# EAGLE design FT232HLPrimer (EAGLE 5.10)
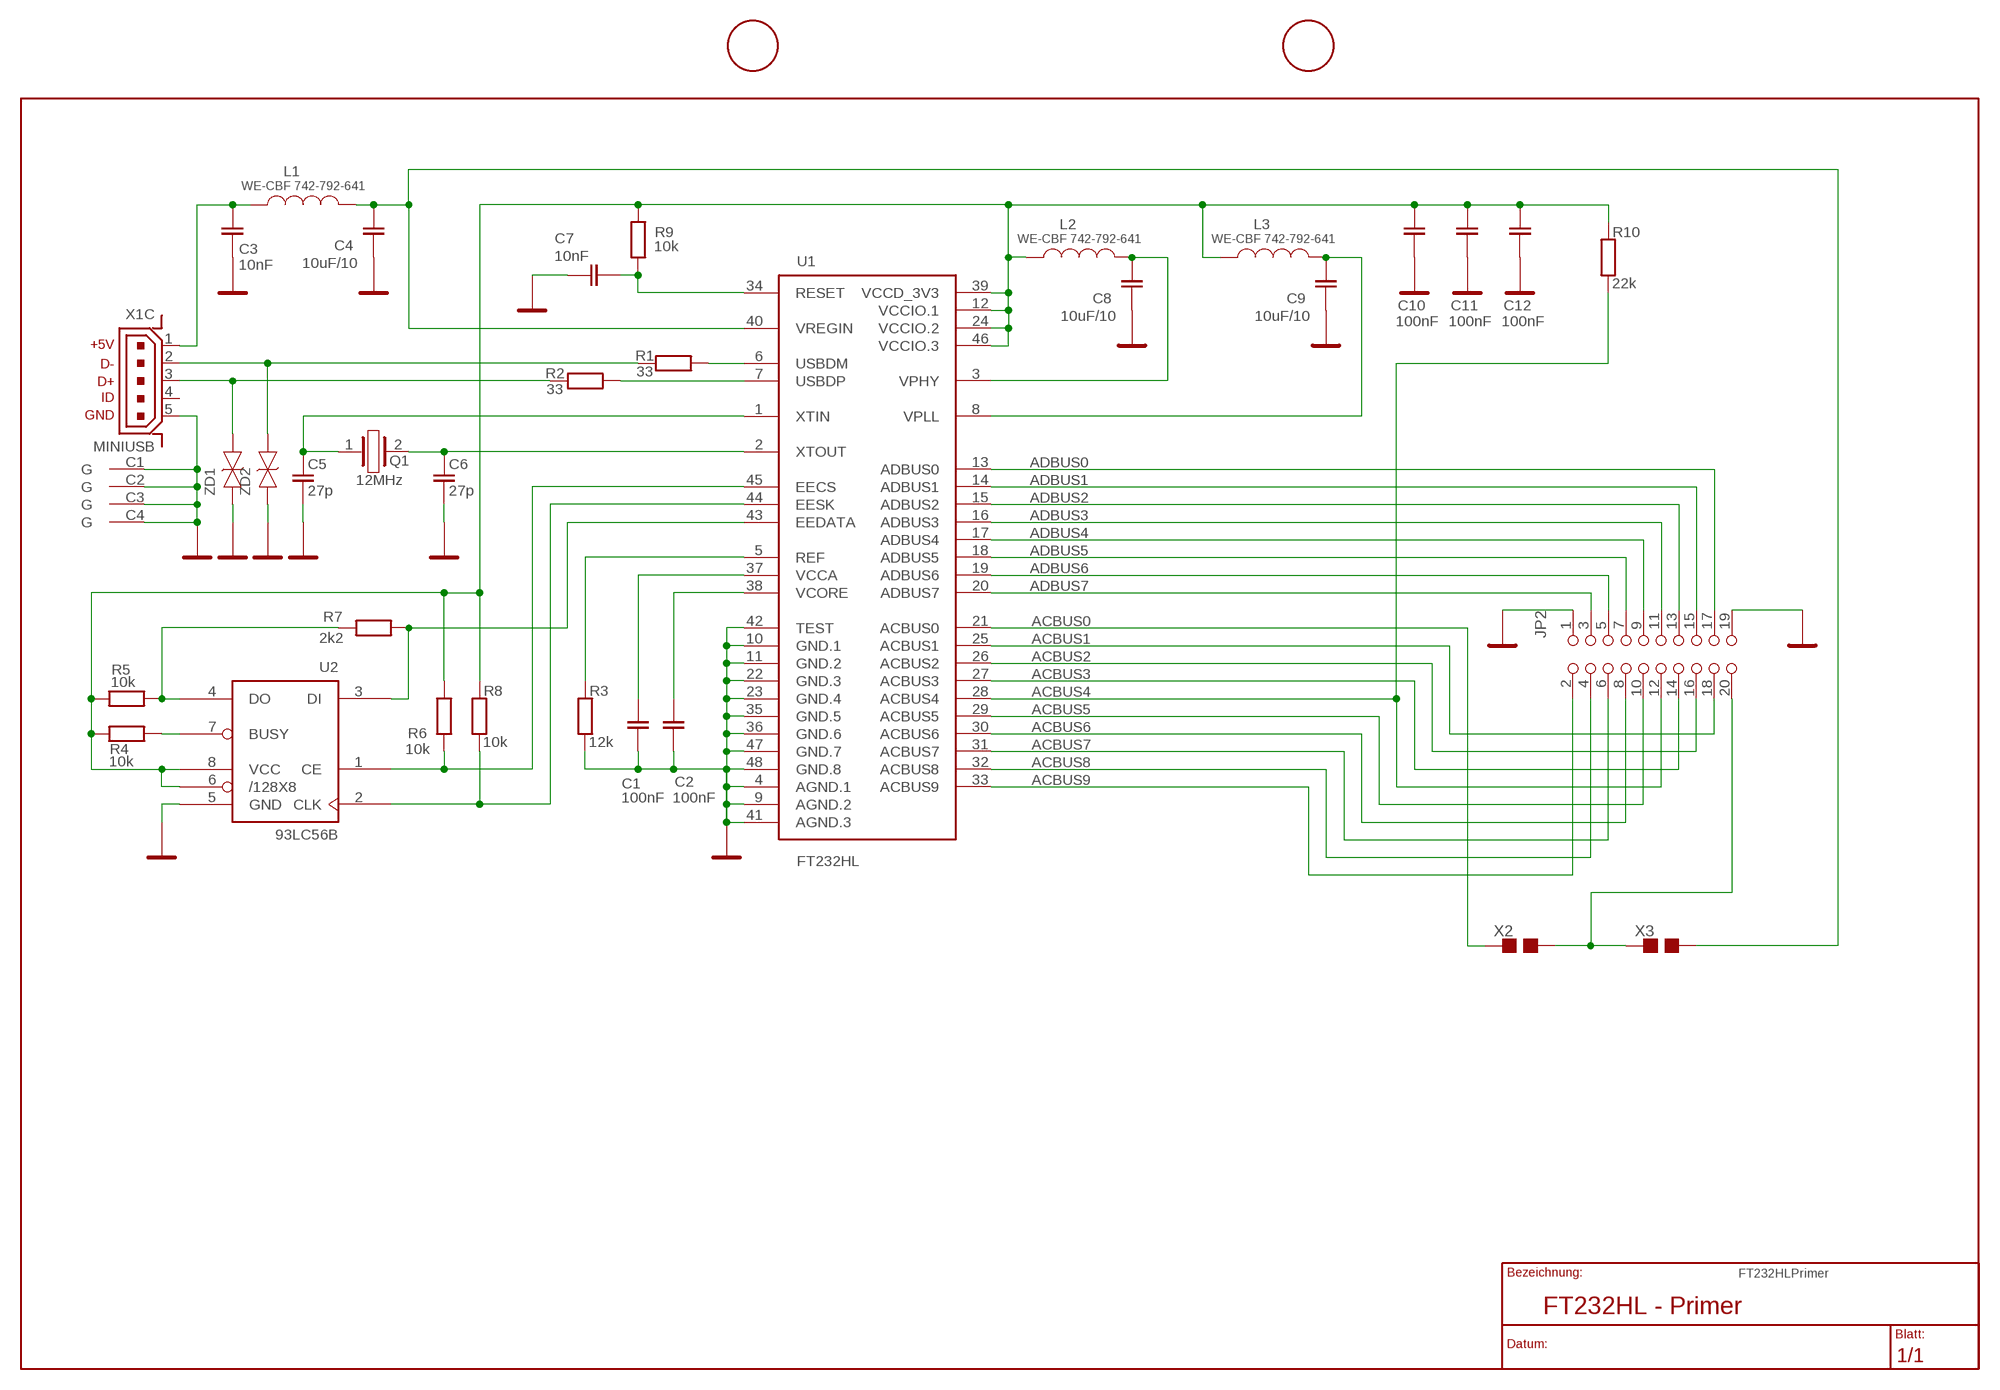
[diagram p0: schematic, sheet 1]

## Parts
C1  100nF  SMD-0603  [SOT-0603]
C2  100nF  SMD-0603  [SOT-0603]
C3  10nF  SMD-0603  [SOT-0603]
C4  10uF/10  SMD-0805  [SOT-0805]
C5  27p  SMD-0603  [SOT-0603]
C6  27p  SMD-0603  [SOT-0603]
C7  10nF  SMD-0603  [SOT-0603]
C8  10uF/10  SMD-0805  [SOT-0805]
C9  10uF/10  SMD-0805  [SOT-0805]
C10  100nF  SMD-0603  [SOT-0603]
C11  100nF  SMD-0603  [SOT-0603]
C12  100nF  SMD-0603  [SOT-0603]
JP2  PINHD-2X10'/90'  [2X10/90]
L1  WE-CBF 742-792-641  SMD-0603  [SMD-0603]
L2  WE-CBF 742-792-641  SMD-0603  [SMD-0603]
L3  WE-CBF 742-792-641  SMD-0603  [SMD-0603]
Q1  12MHz  XTAL'SMD5X3'  [XTAL5X3]
R1  33  SMD-0603  [SMD-0603]
R2  33  SMD-0603  [SMD-0603]
R3  12k  SMD-0603  [SMD-0603]
R4  10k  SMD-0603  [SMD-0603]
R5  10k  SMD-0603  [SMD-0603]
R6  10k  SMD-0603  [SMD-0603]
R7  2k2  SMD-0603  [SMD-0603]
R8  10k  SMD-0603  [SMD-0603]
R9  10k  SMD-0603  [SMD-0603]
R10  22k  SMD-0603  [SMD-0603]
U1  FT232HL  [LQFP48]
U2  93LC56B  93LC66'SO'  [SO-8]
X1  MINIUSB  [UX60A-MB-5SY]
X2  PATCH  [PATCH]
X3  PATCH  [PATCH]
ZD1  PGB1010603  [SUPP0603]
ZD2  PGB1010603  [SUPP0603]

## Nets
ACBUS0: U1.21(ACBUS0) X2.1
ACBUS1: JP2.18 U1.25(ACBUS1)
ACBUS2: JP2.16 U1.26(ACBUS2)
ACBUS3: JP2.14 U1.27(ACBUS3)
ACBUS4: JP2.12 R10.1 U1.28(ACBUS4)
ACBUS5: JP2.10 U1.29(ACBUS5)
ACBUS6: JP2.8 U1.30(ACBUS6)
ACBUS7: JP2.6 U1.31(ACBUS7)
ACBUS8: JP2.4 U1.32(ACBUS8)
ACBUS9: JP2.2 U1.33(ACBUS9)
ADBUS0: JP2.17 U1.13(ADBUS0)
ADBUS1: JP2.15 U1.14(ADBUS1)
ADBUS2: JP2.13 U1.15(ADBUS2)
ADBUS3: JP2.11 U1.16(ADBUS3)
ADBUS4: JP2.9 U1.17(ADBUS4)
ADBUS5: JP2.7 U1.18(ADBUS5)
ADBUS6: JP2.5 U1.19(ADBUS6)
ADBUS7: JP2.3 U1.20(ADBUS7)
CLK: R8.1 U1.44(EESK) U2.2(CLK)
CS: R6.1 U1.45(EECS) U2.1(CE)
D+: R2.2 X1.3 ZD1.2(K)
D-: R1.2 X1.2 ZD2.2(K)
DATA: R7.2 U1.43(EEDATA) U2.3(DI)
GND: C1.1 C2.1 C3.1 C4.1 C5.1 C6.1 C7.1 C8.1 C9.1 C10.1 C11.1 C12.1 JP2.1 JP2.19 R3.1 U1.4(AGND.1) U1.9(AGND.2) U1.10(GND.1) U1.11(GND.2) U1.22(GND.3) U1.23(GND.4) U1.35(GND.5) U1.36(GND.6) U1.41(AGND.3) U1.42(TEST) U1.47(GND.7) U1.48(GND.8) U2.5(GND) X1.5 X1.C1(G) X1.C2(G) X1.C3(G) X1.C4(G) ZD1.1(A) ZD2.1(A)
N$3: R1.1 U1.6(USBDM)
N$4: R2.1 U1.7(USBDP)
N$5: JP2.20 X2.2 X3.1
N$10: C5.2 Q1.1 U1.1(XTIN)
N$11: C6.2 Q1.2 U1.2(XTOUT)
N$12: R5.1 R7.1 U2.4(DO)
N$17: R4.1 U2.7(BUSY)
REF: R3.2 U1.5(REF)
RESET: C7.2 R9.2 U1.34(RESET)
VBUS: C3.2 L1.1 X1.1
VBUS_5V: C4.2 L1.2 U1.40(VREGIN) X3.2
VCCA: C1.2 U1.37(VCCA)
VCCIO: C10.2 C11.2 C12.2 L2.1 L3.1 R4.2 R5.2 R6.2 R8.2 R9.1 R10.2 U1.12(VCCIO.1) U1.24(VCCIO.2) U1.39(VCCD_3V3) U1.46(VCCIO.3) U2.6(/128X8) U2.8(VCC)
VCORE: C2.2 U1.38(VCORE)
VPHY: C8.2 L2.2 U1.3(VPHY)
VPLL: C9.2 L3.2 U1.8(VPLL)
Unconnected: X1.4

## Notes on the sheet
- FT232HL - Primer

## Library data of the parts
C1-C3 C5-C7 C10-C12 = C_KERAM:SMD-0603
C4 C8 C9 = C_KERAM:SMD-0805
JP2 = PINHD-Q:PINHD-2X10
L1-L3 = L:SMD-0603
Q1 = Z_SPECIA:XTAL
R1-R10 = R:SMD-0603
U1 = FTDI:FT232HL
U2 = MIC_CHIP:93LC66
X1 = mini-usb:MINIUSB
X2 X3 = Z_CONNEC:PATCH
ZD1 ZD2 = DIODEN:PGB1010603: Suppressordiode (USB usw.)

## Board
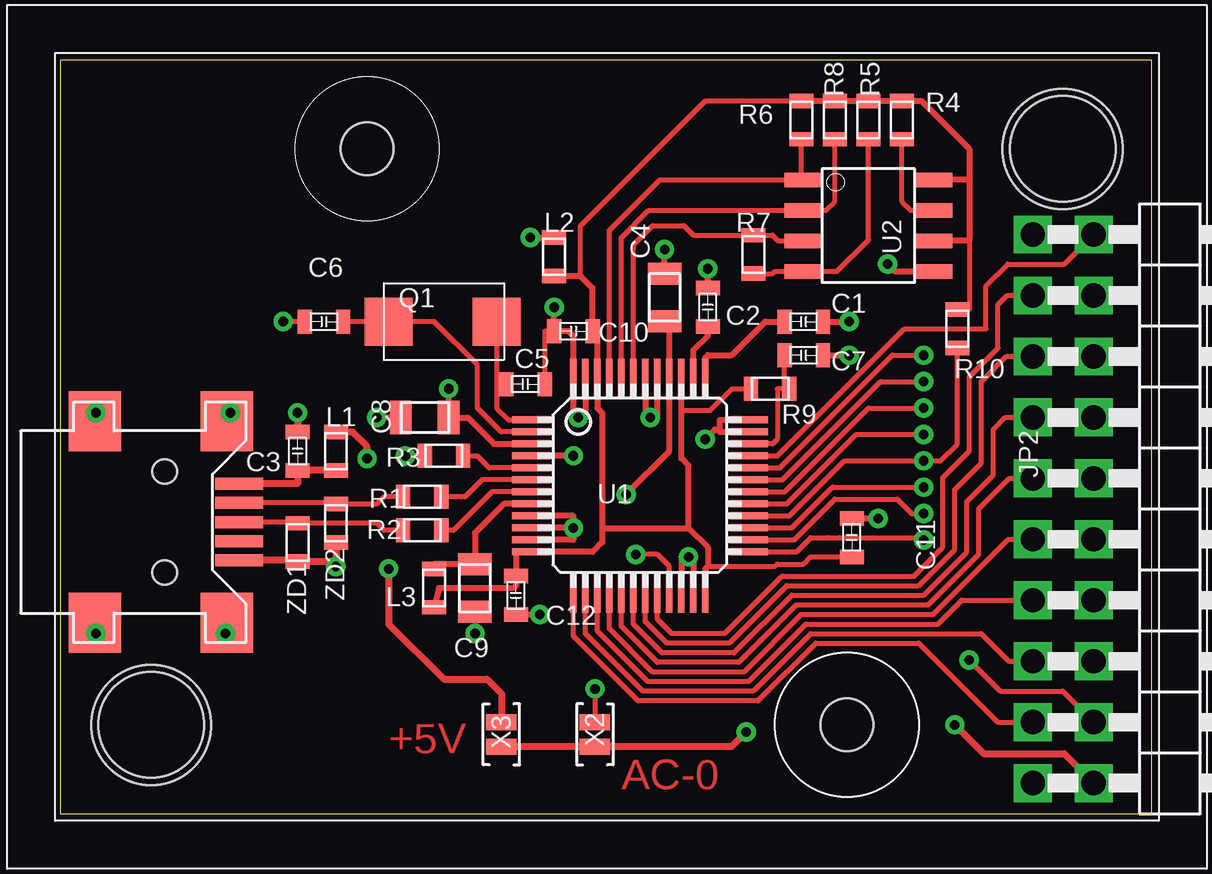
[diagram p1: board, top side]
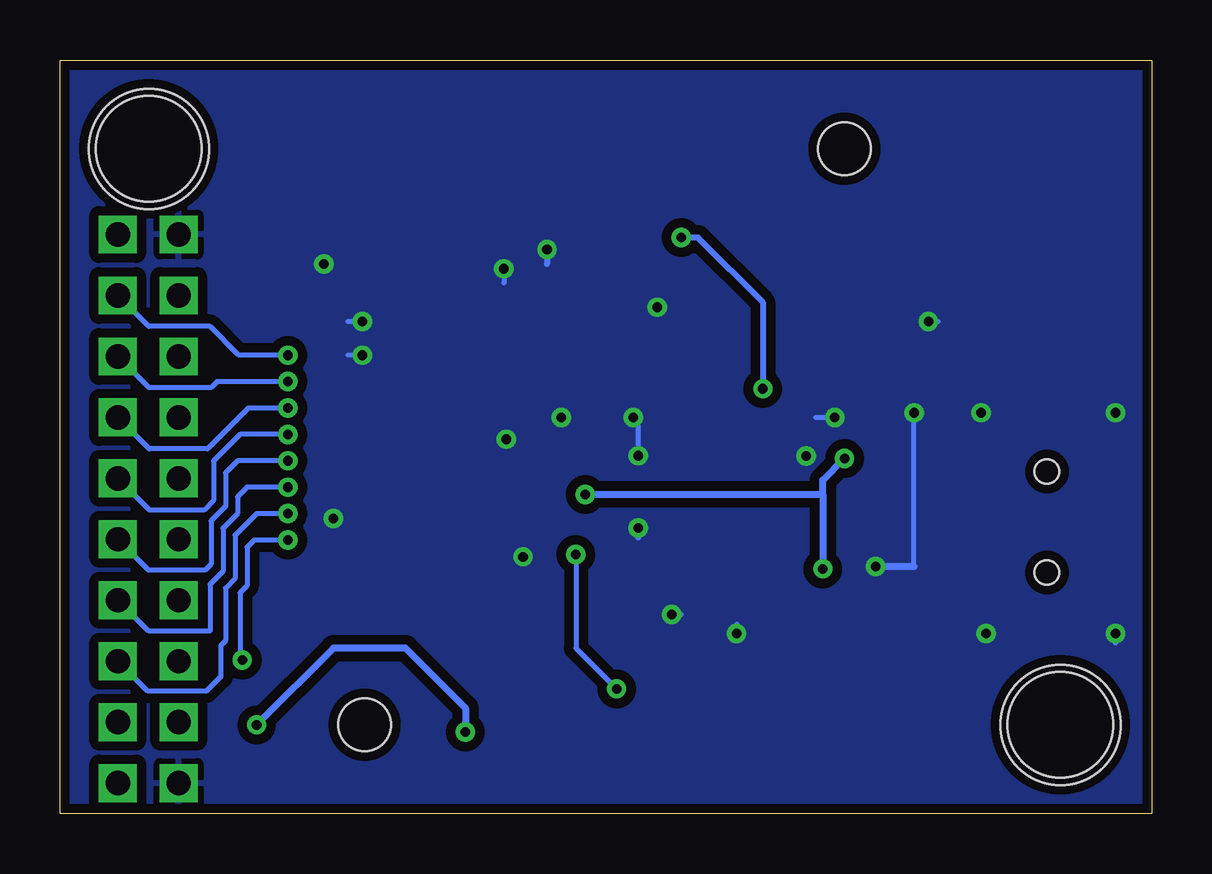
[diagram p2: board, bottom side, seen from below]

Size 45.5 x 31.4 mm. Coordinates in mm from the lower left corner, seen from the top.
Outline: 0,0 45.5,0 45.5,31.4 0,31.4 0,0
Copper layers (1*16): Top 0.035mm / dielectric 1.5mm / Bottom 0.035mm
Design rules "default": minimum track width 0.15mm, minimum drill 0.3mm, track to track 0.15mm, track to pad 0.15mm, pad to pad 0.15mm, via to via 0.15mm, smd to smd 0mil, copper to edge 0.15mm, drill to drill 0.15mm, minimum pad ring 0.15mm, minimum via ring 0.15mm, stop-mask expansion 4mil, vias tented up to drill 0mil, thermal gap 10mil
Holes 5 mm at 3.8,3.7 41.8,27.7

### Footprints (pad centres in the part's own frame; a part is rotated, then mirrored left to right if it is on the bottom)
SOT-0603 = smd 0.6 x 1: 1 -0.8,0; 2 0.8,0
SOT-0805 = smd 0.914 x 1.397: 1 -0.991,0; 2 0.991,0
2X10/90 = drill 1.016 pad 1.575 square: 1 -11.43,-6.35; 2 -11.43,-3.81; 3 -8.89,-6.35; 4 -8.89,-3.81; 5 -6.35,-6.35; 6 -6.35,-3.81; 7 -3.81,-6.35; 8 -3.81,-3.81; 9 -1.27,-6.35; 10 -1.27,-3.81; 11 1.27,-6.35; 12 1.27,-3.81; 13 3.81,-6.35; 14 3.81,-3.81; 15 6.35,-6.35; 16 6.35,-3.81; 17 8.89,-6.35; 18 8.89,-3.81; 19 11.43,-6.35; 20 11.43,-3.81
SMD-0603 = smd 0.6 x 1: 1 -0.8,0; 2 0.8,0
XTAL5X3 = smd 2 x 2: 1 -2.2,0; 2 2.3,0
LQFP48 = smd 1.6 x 0.28: 1 -4.5,2.75; 2 -4.5,2.25; 3 -4.5,1.75; 4 -4.5,1.25; 5 -4.5,0.75; 6 -4.5,0.25; 7 -4.5,-0.25; 8 -4.5,-0.75; 9 -4.5,-1.25; 10 -4.5,-1.75; 11 -4.5,-2.25; 12 -4.5,-2.75; 25 4.55,-2.75; 26 4.55,-2.25; 27 4.55,-1.75; 28 4.55,-1.25; 29 4.55,-0.75; 30 4.55,-0.25; 31 4.55,0.25; 32 4.55,0.75; 33 4.55,1.25; 34 4.55,1.75; 35 4.55,2.25; 36 4.55,2.75 | smd 0.28 x 1.6: 13 -2.75,-4.5; 14 -2.25,-4.5; 15 -1.75,-4.5; 16 -1.25,-4.5; 17 -0.75,-4.5; 18 -0.25,-4.5; 19 0.25,-4.5; 20 0.75,-4.5; 21 1.25,-4.5; 22 1.75,-4.5; 23 2.25,-4.5; 24 2.75,-4.5; 37 2.75,4.5; 38 2.25,4.5; 39 1.75,4.5; 40 1.25,4.5; 41 0.75,4.5; 42 0.25,4.5; 43 -0.25,4.5; 44 -0.75,4.5; 45 -1.25,4.5; 46 -1.75,4.5; 47 -2.25,4.5; 48 -2.75,4.5
SO-8 = smd 0.61 x 1.524: 1 -1.905,-2.743; 2 -0.635,-2.743; 3 0.635,-2.743; 4 1.905,-2.743; 5 1.905,2.743; 6 0.635,2.743; 7 -0.635,2.743; 8 -1.905,2.743
KM201B = hole 4.4: -19,-12; 19,12 | hole 2.2: -10,12; 10,-12
UX60A-MB-5SY = smd 0.5 x 2: 1 -1.6,3.1; 2 -0.8,3.1; 3 0,3.1; 4 0.8,3.1; 5 1.6,3.1 | smd 2.5 x 2.2: C1 -4.2,2.6; C2 -4.2,-2.9; C3 4.2,-2.9; C4 4.2,2.6 | hole 1.016: -2.1,0; 2.1,0
PATCH = smd 0.66 x 1.27: 1 -0.508,0; 2 0.508,0
SUPP0603 = smd 0.6 x 1: 1 -0.8,0; 2 0.8,0

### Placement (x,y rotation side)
C1  31,20.5 180 top
C2  27,21.1 270 top
C3  9.9,15.1 270 top
C4  25.2,21.5 270 top
C5  19.4,17.9 180 top
C6  11,20.5 0 top
C7  31,19.1 180 top
C8  15.2,16.5 0 top
C9  17.3,9.4 90 top
C10  21.4,20.1 0 top
C11  33,11.5 270 top
C12  19,9.1 90 top
JP2  46.9,12.7 270 top
L1  11.5,15.1 90 top
L2  20.6,23.2 90 top
L3  15.6,9.4 90 top
Q1  16,20.5 180 top
R1  15.1,13.2 180 top
R2  15.1,11.8 180 top
R3  16,14.91 0 top
R4  35.1,28.9 90 top
R5  33.7,28.9 90 top
R6  30.9,28.9 90 top
R7  28.9,23.3 90 top
R8  32.3,28.9 90 top
R9  29.6,17.7 0 top
R10  37.4,20.2 90 top
U1  24.15,13.66 0 top
U2  33.7,24.5 270 top
U$21  [KM201B]  22.8,15.7 0 top
X1  4.36,12.15 270 top
X2  22.3,3.3 270 top
X3  18.4,3.3 90 top
ZD1  9.9,11.3 90 top
ZD2  11.5,12.1 90 top

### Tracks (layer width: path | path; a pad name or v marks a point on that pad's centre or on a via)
ACBUS0  (via drill 0.4 pad 0.8)
  Top 0.2: U1.21 25.4,10.3 24.9,10.8 v24,10.8 | v22.3,5.2 X2.1
  Bottom 0.2: v24,10.8 24,6.9 v22.3,5.2
ACBUS1  (via drill 0.4 pad 0.8)
  Top 0.2: U1.25 30.71,10.91 31.3,11.5 32,11.5 32.5,11.5 35.9,11.5 v36,11.4 | JP2.18 41.8,5.1 39.2,5.1 v37.9,6.4
  Bottom 0.2: v37.9,6.4 38,6.5 38,9.2 37.7,9.5 37.7,11.1 37.4,11.4 v36,11.4
ACBUS2  (via drill 0.4 pad 0.8)
  Top 0.2: U1.26 30.61,11.41 32.3,13.1 34.9,13.1 35.5,12.5 v36,12.5
  Bottom 0.2: JP2.16 41.84,5.1 39.4,5.1 38.8,5.7 38.8,7 38.6,7.2 38.6,9.4 38.2,9.8 38.2,11.6 37.3,12.5 v36,12.5
ACBUS3  (via drill 0.4 pad 0.8)
  Top 0.2: U1.27 30.51,11.91 32.2,13.6 v36,13.6
  Bottom 0.2: JP2.14 41.8,7.6 39.25,7.6 39.25,9.55 38.7,10.1 38.7,11.9 38.1,12.5 38.1,13.2 37.7,13.6 v36,13.6
ACBUS4  (via drill 0.4 pad 0.8)
  Top 0.2: U1.28 30.41,12.41 32.7,14.7 v36,14.7 36.7,14.7 37.4,15.4 37.4,16.1 R10.1
  Bottom 0.2: JP2.12 41.81,10.15 39.45,10.15 39.2,10.4 39.2,12.2 38.6,12.8 38.6,14.2 38.1,14.7 v36,14.7
ACBUS5  (via drill 0.4 pad 0.8)
  Top 0.2: U1.29 30.31,12.91 33.2,15.8 v36,15.8
  Bottom 0.2: JP2.10 41.77,12.65 39.5,12.65 39.1,13.05 39.1,14.7 38,15.8 v36,15.8
ACBUS6  (via drill 0.4 pad 0.8)
  Top 0.2: U1.30 30.21,13.41 33.7,16.9 v36,16.9
  Bottom 0.2: JP2.8 41.78,15.2 39.35,15.2 37.65,16.9 v36,16.9
ACBUS7  (via drill 0.4 pad 0.8)
  Top 0.2: U1.31 30.11,13.91 34.2,18 v36,18
  Bottom 0.2: JP2.6 41.79,17.75 39.2,17.75 38.95,18 v36,18
ACBUS8  (via drill 0.4 pad 0.8)
  Top 0.2: U1.32 30.01,14.41 34.7,19.1 v36,19.1
  Bottom 0.2: JP2.4 41.8,20.3 39.25,20.3 38.05,19.1 v36,19.1
ACBUS9
  Top 0.2: U1.33 29.91,14.91 35.2,20.2 36.8,20.2 38.6,20.2 38.6,22 39.5,22.9 41.86,22.9 JP2.2
ADBUS0
  Top 0.2: U1.13 21.4,7.4 24.1,4.7 29.1,4.7 31.5,7.1 35.8,7.1 39.09,3.81 JP2.17
ADBUS1
  Top 0.2: U1.14 21.9,7.5 24.3,5.1 28.9,5.1 31.3,7.5 38.4,7.5 39.55,6.35 JP2.15
ADBUS2
  Top 0.2: U1.15 22.4,7.6 24.5,5.5 28.7,5.5 31.1,7.9 36.6,7.9 37.59,8.89 JP2.13
ADBUS3
  Top 0.2: U1.16 22.9,7.7 24.7,5.9 28.5,5.9 30.9,8.3 36.4,8.3 39.53,11.43 JP2.11
ADBUS4
  Top 0.2: U1.17 23.4,7.8 24.9,6.3 28.3,6.3 30.7,8.7 36.2,8.7 38.3,10.8 38.3,12.7 39.57,13.97 JP2.9
ADBUS5
  Top 0.2: U1.18 23.9,7.9 25.1,6.7 28.1,6.7 30.5,9.1 36,9.1 37.8,10.9 37.8,13 38.9,14.1 38.9,16 39.41,16.51 JP2.7
ADBUS6
  Top 0.2: U1.19 24.4,8 25.3,7.1 27.9,7.1 30.3,9.5 35.8,9.5 37.3,11 37.3,13.5 38.4,14.6 38.4,18 39.45,19.05 JP2.5
ADBUS7
  Top 0.2: U1.20 24.9,8.1 25.5,7.5 27.7,7.5 30.1,9.9 35.6,9.9 36.8,11.1 36.8,14 37.9,15.1 37.9,18.2 39.1,19.4 39.1,21.2 39.49,21.59 JP2.3
CLK
  Top 0.2: R8.1 32.3,25.5 31.94,25.13 U2.2 24.54,25.13 23.4,24 U1.44
CS
  Top 0.2: R6.1 30.9,26.41 U2.1 25.01,26.41 22.9,24.3 U1.45
D+
  Top 0.2: X1.3 9.9,12.15 ZD1.2 13,12.1 13.2,12.1 13.5,11.8 R2.2
D-
  Top 0.2: X1.2 11.5,12.95 ZD2.2 13,12.9 13.2,12.9 13.5,13.2 R1.2
DATA
  Top 0.2: U2.3 29.94,23.86 29.7,24.1 R7.2 26.4,24.1 26,24.5 24.7,24.5 23.9,23.7 U1.43
GND  (via drill 0.4 pad 0.8)
  Top 0.2: 24.4,16.5 v24.6,16.5 | v21.4,11.9 v21.4,11.91 | ZD1.1 9.9,10.55 | X1.C3 1.46,7.54 v1.5,7.5 | X1.C4 6.96,7.56 v6.9,7.5 | X1.C2 1.46,16.66 v1.5,16.7 | X1.C1 6.96,16.56 v7.1,16.7 | R3.1 v14.41,14.91 v14.4,14.9 | U1.10 | C9.1 v17.3,7.5 | C5.1 20.2,20.1 C10.1 | C6.1 v9.3,20.5
  Top 0.25: v21.4,14.91 U1.4 | U1.47 21.9,16.5 v21.6,16.5 21.4,16.5 U1.48 21.4,19.9 21.2,20.1 C10.1 v20.6,21.1 | U1.41 24.9,16.5 v24.6,16.5 | U1.42 24.4,16.5 | U1.35 27.5,15.91 27.5,16 | U1.36 27.5,16.41 27.5,16 | v26.9,15.6 27.3,16 27.5,16 | U1.11 21.4,11.41 v21.4,11.9 21.4,12.41 U1.9 | v21.4,11.91 U1.10 | U1.23 26.4,10.7 v26.2,10.7 25.9,10.7 U1.22 | C11.1 v34.1,12.3 | U2.5 34.8,22.59 v34.5,22.9 | C8.1 v13.2,16.5 | C12.1 v20,8.3 | C4.1 v25.2,23.5 | C2.1 v27,22.7 | C1.1 v32.9,20.5 | C7.1 v32.9,19.1
  Top 0.3: 9.9,10.55 X1.5 | 11.5,10.5 ZD1.1 | 11.5,10.5 v11.5,10.3 | ZD2.1 11.5,10.5 | v9.9,16.7 C3.1
  Bottom 0.2: v21.4,14.91 21.4,16.5 v21.6,16.5 | v26.9,15.6 26.6,15.6 | v26.2,10.7 26.2,10.9 | 9.9,10.3 v9.9,16.7 | v1.5,7.5 1.5,7.1 | v6.9,7.5 6.9,7.3 | v1.5,16.7 1.5,16.9 | v7.1,16.7 7.1,16.9 | v14.4,14.9 14.6,14.9 | v34.1,12.3 33.8,12.3 | v34.5,22.9 34.3,23.1 | v13.2,16.5 14,16.5 | v17.3,7.5 17.3,7.9 | v20,8.3 19.6,8.3 | v27,22.7 27,22.1 | v32.9,20.5 33.5,20.5 | v32.9,19.1 33.5,19.1 | v9.3,20.5 8.9,20.5
  Bottom 0.25: v24.6,16.5 24.8,16.5 | v21.4,11.9 21.4,11.5 | v25.2,23.5 25.2,22.9
  Bottom 0.3: v11.5,10.3 9.9,10.3
  pour Bottom (isolate 0.4): 0.3,31 45.4,31 45.4,0.4 0.3,0.4
N$3
  Top 0.2: U1.6 17.59,13.91 16.88,13.2 16.7,13.2 16.5,13.2 R1.1
N$4
  Top 0.2: U1.7 18.01,13.41 16.4,11.8 R2.1
N$5  (via drill 0.4 pad 0.8)
  Top 0.3: JP2.20 41.86,2.5 38.5,2.5 v37.3,3.7 | v28.6,3.4 27.99,2.79 X2.2 X3.1
  Bottom 0.3: v37.3,3.7 34.1,6.9 31.1,6.9 28.6,4.4 v28.6,3.4
N$10
  Top 0.2: U1.1 18.69,16.41 18.2,16.9 18.2,17.9 | Q1.1 18.2,17.9 | 18.2,17.9 C5.2
N$11
  Top 0.2: U1.2 18.39,15.91 17.4,16.9 17.4,18.7 15.6,20.5 Q1.2 C6.2
N$12
  Top 0.2: R5.1 33.7,23.9 32.4,22.59 U2.4 29.8,22.59 29.7,22.5 R7.1
N$17
  Top 0.2: U2.7 35.47,25.13 35.1,25.5 R4.1
REF
  Top 0.2: U1.5 17.89,14.41 17.4,14.9 R3.2
RESET
  Top 0.2: C7.2 30.2,17.9 R9.2 29.9,17.7 29.9,15.6 29.71,15.41 U1.34
VBUS
  Top 0.3: X1.1 9.9,13.75 C3.2 L1.1
VBUS_5V  (via drill 0.4 pad 0.8)
  Top 0.25: v23.6,13.3 25.4,15.1 U1.40 25.4,20.11 C4.2
  Top 0.3: L1.2 12.2,15.9 12.8,15.3 v12.8,14.8 | X3.2 18.4,5 17.8,5.6 16,5.6 13.7,7.9 v13.7,10.2
  Bottom 0.3: 13.7,13.3 13.7,13.9 v12.8,14.8 | v23.6,13.3 13.7,13.3 | 13.7,13.3 v13.7,10.2
VCCA
  Top 0.25: U1.37 26.9,19 27,19.1 28,19.1 29.4,20.5 29.9,20.5 C1.2
VCCIO
  Top 0.2: 22.4,20.1 C10.2 | U2.8 36.5,26.41 | R9.1 28,17.7 27.1,16.8 25.9,16.8 | R6.2 26.9,29.7 21.7,24.5 21.7,22.4 | C11.2 31.3,10.7 31,10.4 29.9,10.4 29.8,10.3 27,10.3 | R10.2 37.9,21 37.9,23.86
  Top 0.25: 22.6,11.9 22.6,11.3 22.21,10.91 U1.12 19,10.91 C12.2 19,9.5 18.9,9.4 15.8,9.4 L3.1 | 22.6,11.9 22.6,16.7 22.4,16.9 U1.46 22.4,20.1 | U1.24 26.9,10.2 27,10.3 27,11.1 26.2,11.9 | 22.6,11.9 26.2,11.9 | U1.39 25.9,16.8 25.9,14.8 26.2,14.5 26.2,11.9 | R6.2 R8.2 R5.2 R4.2 35.9,29.7 37.9,27.7 37.9,26.41 | 37.9,26.41 U2.8 | U2.6 37.9,23.86 37.9,26.41 | C10.2 22.2,21.9 21.7,22.4 L2.1
VCORE
  Top 0.25: U1.38 26.4,19.3 27,19.9 C2.2
VPHY  (via drill 0.4 pad 0.8)
  Top 0.25: U1.3 18.09,15.41 17,16.5 C8.2 v16.19,17.69 v16.2,17.7 | v19.6,24 L2.2
  Bottom 0.25: v16.2,17.7 16.2,21.3 18.9,24 v19.6,24
VPLL
  Top 0.25: U1.8 18.51,12.91 17.3,11.7 C9.2 16.1,10.4 15.6,10.4 L3.2

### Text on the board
Top: +5V | AC-0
